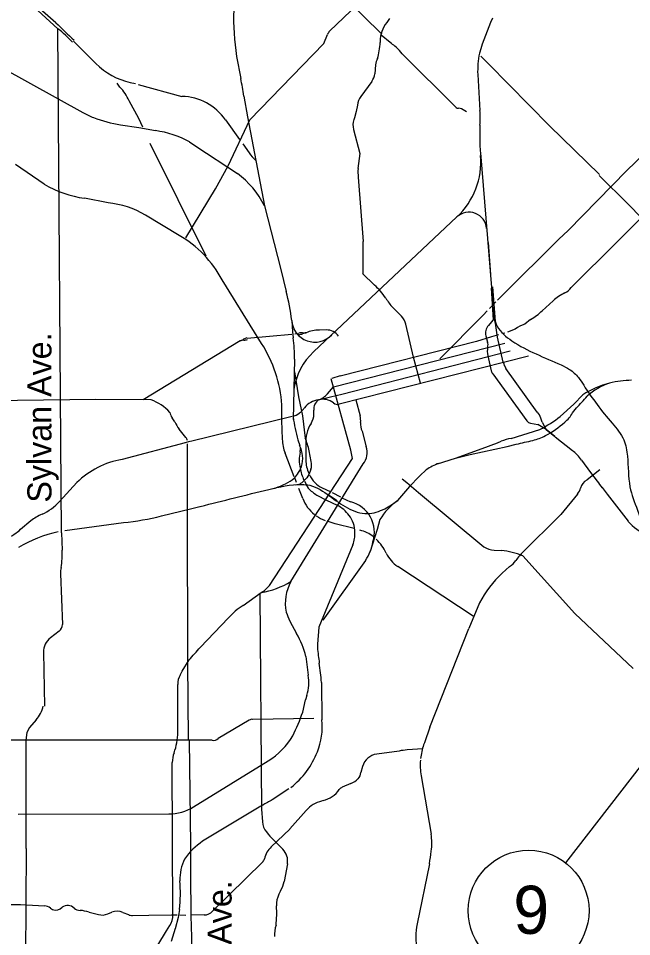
# Model space of a CAD drawing. Extents: x 105094 to 105814, y -291615 to -291123.
# Drawn here: x 105428.3 to 105459.11, y -291494.14 to -291448.01 of the extents above; entities that cross this region are included whole.
import ezdxf

# ---------------------------------------------------------------- set-up
doc = ezdxf.new("R2010")
doc.units = 0
doc.layers.add('G_BORDER', color=7, linetype='Continuous')
doc.layers.add('G_MAP', color=7, linetype='Continuous')

msp = doc.modelspace()

# ---------------------------------------------------------------- linework, layer by layer
at = {"layer": 'G_BORDER'}
msp.add_line((105461.154, -291483.504), (105455.794, -291490.435), dxfattribs=at)
msp.add_circle((105453.937, -291492.836), 3.035, dxfattribs=at)
at = {"layer": 'G_MAP'}
for p, q in [((105439.683, -291441.953), (105446.556, -291448.806)), ((105443.935, -291448.654), (105446.62, -291446.065)), ((105430.185, -291448.226), (105428.864, -291447.053)), ((105428.871, -291447.247), (105430.285, -291448.523)), ((105446.953, -291448.005), (105446.817, -291448.218)), ((105430.46, -291473.849), (105430.285, -291448.523)), ((105431.07, -291449.156), (105432.194, -291450.276)), ((105443.656, -291449.273), (105443.838, -291448.809)), ((105446.482, -291449.165), (105446.479, -291449.223)), ((105446.985, -291449.219), (105446.527, -291448.842)), ((105439.935, -291453.111), (105443.656, -291449.273)), ((105439.263, -291449.915), (105439.47, -291451.032)), ((105451.539, -291449.91), (105451.923, -291450.298)), ((105427.527, -291450.506), (105431.537, -291452.737)), ((105446.25, -291450.336), (105446.206, -291450.795)), ((105451.38, -291450.827), (105451.494, -291452.633)), ((105433.402, -291451.468), (105433.256, -291451.261)), ((105433.922, -291451.225), (105434.183, -291451.284)), ((105434.316, -291451.335), (105436.518, -291451.923)), ((105446.063, -291451.169), (105445.503, -291451.926)), ((105439.635, -291451.907), (105439.816, -291452.956)), ((105450.809, -291452.698), (105450.558, -291452.553)), ((105433.438, -291453.36), (105434.348, -291453.496)), ((105438.701, -291453.108), (105439.415, -291454.084)), ((105438.837, -291455.417), (105439.935, -291453.111)), ((105439.816, -291452.956), (105440.662, -291457.418)), ((105451.491, -291453.379), (105451.481, -291453.961)), ((105434.348, -291453.496), (105435.191, -291453.644)), ((105445.136, -291453.585), (105445.458, -291454.8)), ((105437.742, -291459.945), (105434.923, -291454.287)), ((105436.906, -291454.21), (105437.209, -291454.419)), ((105439.573, -291454.316), (105439.89, -291454.757)), ((105437.209, -291454.419), (105439.302, -291455.802)), ((105451.513, -291454.755), (105452.074, -291461.522)), ((105445.458, -291454.8), (105445.364, -291455.553)), ((105429.6, -291456.335), (105428.157, -291455.35)), ((105445.377, -291455.989), (105445.626, -291459.218)), ((105432.804, -291457.281), (105431.629, -291457.045)), ((105440.662, -291457.418), (105441.482, -291460.617)), ((105436.379, -291458.909), (105434.69, -291457.895)), ((105450.337, -291457.984), (105443.135, -291464.765)), ((105451.901, -291459.26), (105452.03, -291460.881)), ((105441.482, -291460.617), (105441.757, -291461.731)), ((105440.517, -291464.337), (105438.534, -291461.15)), ((105446.194, -291461.403), (105445.587, -291460.823)), ((105452.124, -291461.495), (105452.269, -291463.449)), ((105452.382, -291462.16), (105452.64, -291461.892)), ((105447.542, -291462.969), (105447.121, -291462.535)), ((105451.965, -291462.577), (105452.285, -291462.244)), ((105455.163, -291462.195), (105454.617, -291462.696)), ((105449.469, -291465.119), (105451.659, -291462.916)), ((105451.659, -291462.916), (105451.852, -291462.693)), ((105452.215, -291463.075), (105451.917, -291463.437)), ((105442.034, -291463.178), (105442.076, -291463.75)), ((105454.039, -291463.136), (105453.742, -291463.362)), ((105442.034, -291463.885), (105439.796, -291464.095)), ((105442.076, -291463.75), (105442.112, -291464.056)), ((105442.396, -291463.859), (105442.189, -291463.876)), ((105443.771, -291463.661), (105443.425, -291463.664)), ((105451.79, -291463.96), (105451.878, -291464.269)), ((105452.421, -291463.898), (105452.078, -291464.014)), ((105452.734, -291463.814), (105452.598, -291463.843)), ((105453.257, -291463.614), (105452.873, -291463.765)), ((105439.444, -291464.205), (105434.564, -291467.17)), ((105444.133, -291466.525), (105452.744, -291464.331)), ((105452.662, -291465.287), (105452.369, -291464.03)), ((105444.544, -291466.885), (105453.018, -291464.712)), ((105442.178, -291465.122), (105442.115, -291468.158)), ((105453.935, -291464.977), (105444.414, -291467.392)), ((105451.883, -291464.954), (105452.06, -291465.708)), ((105442.182, -291465.759), (105442.38, -291467.021)), ((105454.375, -291467.79), (105452.799, -291465.59)), ((105442.244, -291466.291), (105442.27, -291466.411)), ((105445.006, -291469.705), (105444.02, -291466.115)), ((105444.473, -291465.972), (105444.043, -291466.107)), ((105452.132, -291465.865), (105453.846, -291468.224)), ((105443.837, -291466.868), (105444.133, -291466.525)), ((105442.38, -291467.021), (105442.574, -291467.971)), ((105443.384, -291467.173), (105443.982, -291467.028)), ((105443.982, -291467.028), (105444.544, -291466.885)), ((105445.261, -291467.179), (105445.47, -291467.98)), ((105456.661, -291466.924), (105456.206, -291467.396)), ((105441.544, -291468.216), (105441.54, -291467.425)), ((105443.146, -291467.876), (105443.142, -291467.689)), ((105456.206, -291467.396), (105455.531, -291468.003)), ((105456.141, -291467.832), (105456.345, -291467.576)), ((105436.163, -291468.284), (105436.022, -291468.073)), ((105442.057, -291468.006), (105436.951, -291469.263)), ((105442.574, -291467.971), (105442.713, -291469.091)), ((105454.614, -291468.29), (105454.543, -291468.09)), ((105441.563, -291469.152), (105441.544, -291468.216)), ((105454.039, -291468.347), (105454.401, -291468.419)), ((105454.825, -291468.67), (105454.401, -291468.419)), ((105454.614, -291468.29), (105454.825, -291468.67)), ((105436.721, -291469.056), (105436.379, -291468.643)), ((105445.568, -291468.746), (105445.778, -291469.534)), ((105453.054, -291469.107), (105454.501, -291468.658)), ((105454.825, -291468.67), (105455.25, -291469.022)), ((105455.25, -291469.022), (105454.825, -291468.67)), ((105455.269, -291469.03), (105456.136, -291469.712)), ((105436.673, -291469.334), (105433.515, -291470.164)), ((105436.912, -291469.272), (105436.667, -291469.334)), ((105436.796, -291472.777), (105436.799, -291469.389)), ((105442.348, -291469.185), (105442.438, -291469.469)), ((105451.607, -291469.611), (105452.376, -291469.337)), ((105452.376, -291469.337), (105452.553, -291469.246)), ((105452.867, -291469.508), (105453.319, -291469.398)), ((105442.164, -291471.045), (105441.7, -291469.853)), ((105443.019, -291470.272), (105442.913, -291469.728)), ((105450.257, -291470.105), (105451.607, -291469.611)), ((105441.996, -291476.306), (105445.621, -291470.392)), ((105449.362, -291470.387), (105450.257, -291470.105)), ((105448.474, -291470.987), (105448.794, -291470.684)), ((105457.524, -291470.687), (105456.884, -291471.194)), ((105431.235, -291471.33), (105430.368, -291472.278)), ((105442.273, -291471.333), (105442.199, -291471.116)), ((105442.671, -291471.255), (105442.806, -291471.507)), ((105447.586, -291471.145), (105447.815, -291471.32)), ((105447.815, -291471.323), (105448.167, -291471.627)), ((105447.927, -291471.559), (105448.474, -291470.987)), ((105456.884, -291471.194), (105456.859, -291471.208)), ((105442.589, -291472.13), (105442.393, -291471.627)), ((105442.745, -291471.41), (105442.868, -291471.604)), ((105443.571, -291471.593), (105443.969, -291471.782)), ((105444.063, -291471.82), (105444.479, -291472.053)), ((105447.363, -291472.23), (105447.977, -291471.526)), ((105448.164, -291471.627), (105448.406, -291471.83)), ((105448.406, -291471.83), (105451.694, -291474.562)), ((105457.63, -291471.584), (105457.882, -291471.917)), ((105443.302, -291471.963), (105443.782, -291472.205)), ((105443.782, -291472.205), (105444.311, -291472.47)), ((105444.315, -291472.253), (105443.933, -291471.998)), ((105444.554, -291472.101), (105444.996, -291472.292)), ((105457.882, -291471.917), (105458.933, -291473.276)), ((105435.495, -291473.006), (105436.954, -291472.644)), ((105436.812, -291480.334), (105436.796, -291472.777)), ((105436.954, -291472.644), (105437.423, -291472.538)), ((105446.469, -291473.187), (105446.333, -291473.694)), ((105428.925, -291473.255), (105428.412, -291473.678)), ((105430.628, -291473.736), (105433.576, -291473.342)), ((105446.333, -291473.694), (105445.978, -291474.794)), ((105430.46, -291473.849), (105430.5, -291474.721)), ((105445.109, -291474.453), (105443.397, -291478.6)), ((105452.2, -291474.72), (105452.568, -291474.747)), ((105445.749, -291475.241), (105443.598, -291478.244)), ((105451.145, -291478.038), (105447.362, -291475.546)), ((105452.98, -291475.544), (105452.605, -291475.88)), ((105430.418, -291475.908), (105430.51, -291478.463)), ((105439.596, -291477.498), (105440.497, -291476.852)), ((105440.439, -291476.914), (105440.52, -291487.779)), ((105451.471, -291477.379), (105450.932, -291478.667)), ((105437.426, -291479.609), (105438.853, -291478.131)), ((105441.943, -291478.287), (105442.274, -291478.913)), ((105448.978, -291483.612), (105450.932, -291478.667)), ((105430.354, -291478.795), (105429.909, -291479.134)), ((105429.558, -291479.855), (105429.607, -291482.556)), ((105442.745, -291480.072), (105442.858, -291481.002)), ((105436.848, -291484.232), (105436.812, -291480.334)), ((105436.305, -291483.877), (105436.305, -291481.47)), ((105443.533, -291481.367), (105443.549, -291483.247)), ((105442.587, -291482.857), (105442.732, -291482.246)), ((105442.787, -291482.023), (105442.732, -291482.246)), ((105439.903, -291483.267), (105438.337, -291484.19)), ((105443.139, -291483.186), (105440.081, -291483.225)), ((105448.978, -291483.612), (105448.701, -291484.41)), ((105438.04, -291484.271), (105420.577, -291484.284)), ((105428.684, -291489.722), (105428.693, -291484.267)), ((105436.877, -291484.271), (105436.948, -291489.541)), ((105448.63, -291484.7), (105447.832, -291484.759)), ((105448.701, -291484.41), (105448.659, -291484.5)), ((105447.428, -291484.817), (105446.308, -291484.97)), ((105436.06, -291493.039), (105436.034, -291485.395)), ((105437.106, -291487.622), (105440.848, -291485.311)), ((105445.595, -291485.595), (105445.513, -291485.895)), ((105448.532, -291486.056), (105449.037, -291488.986)), ((105445.01, -291486.448), (105444.57, -291486.638)), ((105441.889, -291486.722), (105441.056, -291487.265)), ((105443.617, -291487.309), (105443.536, -291487.33)), ((105428.286, -291487.981), (105435.853, -291487.978)), ((105440.478, -291487.588), (105437.559, -291489.348)), ((105440.517, -291487.739), (105440.559, -291488.374)), ((105442.763, -291487.804), (105441.941, -291488.734)), ((105441.944, -291488.737), (105441.003, -291489.634)), ((105441.111, -291489.273), (105441.587, -291489.752)), ((105428.684, -291489.722), (105428.529, -291514.353)), ((105440.564, -291490.403), (105438.061, -291492.87)), ((105441.814, -291490.489), (105441.65, -291491.366)), ((105448.951, -291490.48), (105448.33, -291493.495)), ((105441.476, -291491.841), (105441.392, -291492.013)), ((105430.4, -291492.74), (105430.503, -291492.668)), ((105431.852, -291492.913), (105432.325, -291493.035)), ((105432.798, -291493), (105432.988, -291492.921)), ((105433.552, -291492.922), (105433.826, -291493.038)), ((105434.028, -291493.078), (105434.859, -291493.071)), ((105434.859, -291493.071), (105435.989, -291493.055)), ((105436.002, -291493.052), (105436.273, -291493.052)), ((105436.383, -291492.88), (105436.322, -291493.178)), ((105436.394, -291492.775), (105436.383, -291492.88)), ((105436.419, -291493.048), (105436.719, -291493.058)), ((105437.627, -291493.052), (105436.968, -291493.061)), ((105436.322, -291493.178), (105436.176, -291493.743)), ((105434.261, -291496.294), (105435.744, -291493.849)), ((105435.744, -291493.849), (105435.909, -291493.586)), ((105436.176, -291493.74), (105435.97, -291494.385))]:
    msp.add_line(p, q, dxfattribs=at)
for points in [[(105471.669, -291445.853), (105471.33, -291446.221), (105468.414, -291449.206), (105465.61, -291451.938), (105463.22, -291454.38), (105458.379, -291459.237), (105456.07, -291461.521)], [(105452.64, -291461.892), (105455.457, -291459.092), (105455.925, -291458.656), (105458.88, -291455.656), (105459.723, -291454.825), (105463.482, -291451.066), (105464.151, -291450.417), (105465.219, -291449.141)], [(105450.291, -291452.486), (105447.583, -291449.785), (105447.444, -291449.613)], [(105451.923, -291450.298), (105454.988, -291453.401), (105457.507, -291455.849)], [(105434.545, -291453.464), (105434.348, -291453.037), (105433.86, -291452.146)], [(105445.345, -291452.366), (105445.345, -291452.372), (105445.277, -291452.691), (105445.196, -291452.995), (105445.159, -291453.095)], [(105436.706, -291459.038), (105438.201, -291456.574), (105438.837, -291455.417)], [(105457.478, -291455.895), (105458.935, -291457.348), (105461.619, -291460.093), (105463.046, -291461.488), (105464.351, -291462.774)], [(105445.619, -291460.823), (105445.629, -291459.958), (105445.626, -291459.218)], [(105452.049, -291461.556), (105452.153, -291463.161), (105452.13, -291463.197)], [(105448.513, -291466.333), (105448.151, -291465.028), (105447.764, -291463.376)], [(105452.075, -291464.004), (105451.319, -291464.243), (105444.473, -291465.978)], [(105434.964, -291467.178), (105432.187, -291467.157), (105424.304, -291467.257), (105420.212, -291467.19)], [(105442.748, -291469.398), (105442.751, -291470.083), (105442.749, -291470.211)], [(105450.257, -291470.105), (105450.993, -291469.921), (105452.867, -291469.508)], [(105440.911, -291476.5), (105445.096, -291470.118), (105445.006, -291469.705)], [(105456.595, -291470.196), (105457.042, -291470.829), (105457.388, -291471.261)], [(105456.398, -291471.903), (105455.554, -291472.941), (105453.571, -291474.905), (105453.477, -291475.009)], [(105445.17, -291473.639), (105444.214, -291473.403), (105443.808, -291473.267)], [(105453.642, -291475.011), (105456.257, -291477.908), (105459.185, -291480.671)], [(105443.397, -291478.6), (105443.323, -291479.446), (105443.323, -291479.623)], [(105436.426, -291480.997), (105436.535, -291480.799), (105436.874, -291480.237)], [(105429.195, -291483.249), (105428.858, -291483.641), (105428.732, -291483.88), (105428.671, -291484.264)], [(105436.948, -291489.541), (105436.948, -291490.972), (105436.971, -291493.09), (105437.006, -291494.166), (105437.006, -291494.818), (105437.01, -291498.067), (105436.971, -291505.559), (105437.013, -291510.468)], [(105427.482, -291492.532), (105428.412, -291492.528), (105429.612, -291492.597)]]:
    msp.add_lwpolyline(points, dxfattribs=at)
for centre, radius, start, end in [((105451.848, -291447.961), 12.736, 178.3296, 188.8235), ((105447.664, -291430.771), 24.701, 224.9607, 227.9176), ((105447.808, -291449.103), 1.327, 138.2348, 182.6801), ((105466.386, -291454.248), 15.582, 156.3243, 163.2541), ((105422.645, -291457.597), 11.862, 45.0555, 49.9037), ((105444.202, -291448.931), 0.384, 133.994, 161.5815), ((105443.104, -291449.065), 3.378, 343.4559, 357.3213), ((105444.53, -291452.541), 4.13, 45.1361, 53.5308), ((105447.054, -291450.409), 0.808, 151.7395, 174.7801), ((105455.916, -291450.648), 4.539, 168.6953, 182.25), ((105434.698, -291447.765), 3.546, 225.0895, 257.3608), ((105424.419, -291454.317), 15.406, 9.0006, 12.3132), ((105445.459, -291450.723), 0.751, 323.509, 354.5267), ((105431.907, -291452.972), 2.121, 22.9368, 45.1968), ((105436.476, -291454.605), 2.682, 33.9214, 89.0875), ((105446.155, -291452.409), 0.811, 143.5258, 176.9523), ((105433.72, -291448.804), 4.498, 240.956, 248.4911), ((105450.389, -291452.385), 0.141, 225.7595, 281.2306), ((105450.444, -291452.751), 0.229, 59.9057, 96.7289), ((105442.98, -291452.969), 8.521, 357.2428, 2.2611), ((105435.026, -291444.819), 8.688, 250.1189, 259.468), ((105445.923, -291453.377), 0.814, 159.7058, 194.7775), ((105434.445, -291458.792), 5.201, 61.7657, 81.7577), ((105458.364, -291454.075), 6.885, 179.0483, 185.6628), ((105442.026, -291453.223), 2.63, 215.6853, 226.8997), ((105447.72, -291455.204), 3.817, 313.2748, 4.7334), ((105447.323, -291455.713), 1.965, 175.3256, 188.0685), ((105436.656, -291459.409), 4.474, 26.432, 53.7392), ((105432.34, -291451.764), 5.329, 239.0627, 262.3292), ((105432.446, -291461.588), 4.322, 58.7155, 85.2448), ((105450.945, -291458.629), 0.886, 4.7334, 133.2748), ((105433.548, -291463.786), 5.64, 27.8676, 59.8615), ((105443.194, -291464.551), 4.349, 34.9388, 46.3783), ((105455.428, -291461.13), 0.752, 296.4072, 328.6737), ((105431.946, -291464.364), 10.158, 6.7077, 15.0247), ((105448.927, -291460.783), 2.516, 210.501, 224.1131), ((105456.648, -291463.813), 2.196, 113.7889, 132.5456), ((105446.92, -291463.573), 0.867, 13.1391, 44.1335), ((105446.36, -291464.498), 6.028, 4.4503, 13.6063), ((105452.287, -291460.23), 3.393, 301.0858, 313.3698), ((105443.197, -291463.106), 1.165, 183.5224, 316.8845), ((105452.312, -291463.81), 0.543, 136.566, 195.9371), ((105454.799, -291465.986), 2.829, 111.9397, 123.0151), ((105442.522, -291464.593), 0.786, 86.3427, 99.7128), ((105442.271, -291463.126), 0.786, 279.7128, 293.083), ((105442.622, -291463.023), 0.786, 266.3427, 279.7129), ((105442.887, -291464.573), 0.786, 99.7128, 113.083), ((105443.446, -291465.517), 1.853, 90.6471, 111.8946), ((105443.779, -291464.423), 0.763, 36.5429, 90.6383), ((105439.204, -291463.434), 0.808, 287.3242, 300.5132), ((105439.685, -291464.976), 0.808, 94.1351, 107.3242), ((105440.024, -291464.826), 0.808, 107.3242, 120.5133), ((105439.568, -291463.365), 0.808, 274.1351, 287.3241), ((105434.989, -291467.884), 6.567, 4.006, 32.6848), ((105431.902, -291465.221), 10.276, 0.5487, 6.5068), ((105451.393, -291464.408), 0.505, 346.6504, 16.0118), ((105445.226, -291467.065), 3.109, 132.282, 172.151), ((105452.792, -291464.741), 0.934, 166.6319, 193.1952), ((105453.492, -291465.094), 0.852, 193.086, 215.6061), ((105452.485, -291465.608), 0.437, 193.2388, 216.0236), ((105459.536, -291473.779), 7.608, 93.1821, 101.6109), ((105459.167, -291470.749), 4.573, 104.7259, 123.2294), ((105459.118, -291469.5), 3.363, 109.3325, 131.777), ((105434.217, -291469.345), 2.292, 42.3205, 70.9785), ((105443.498, -291468.2), 1.033, 96.3374, 142.876), ((105443.679, -291467.626), 0.54, 122.9949, 186.6814), ((105442.975, -291466.075), 1.172, 290.4657, 317.4066), ((105443.605, -291468.016), 0.871, 52.7395, 104.6959), ((105449.423, -291460.732), 9.734, 315.3206, 319.9777), ((105441.997, -291467.065), 0.849, 311.6063, 322.9384), ((105444.338, -291467.094), 0.307, 228.0877, 284.1637), ((105434.43, -291468.065), 1.505, 9.8617, 10.1015), ((105436.635, -291467.664), 0.737, 191.2113, 213.6497), ((105450.769, -291466.824), 8.746, 188.0304, 195.6625), ((105441.879, -291467.151), 0.87, 288.8397, 314.2527), ((105442.303, -291467.898), 0.843, 326.4954, 1.5496), ((105444.577, -291468.214), 0.924, 353.977, 14.7047), ((105454.088, -291468.147), 0.459, 7.1799, 51.2401), ((105451.497, -291462.802), 6.582, 297.1505, 307.7962), ((105454.883, -291467.155), 1.428, 307.3909, 331.7423), ((105438.255, -291467.266), 2.327, 205.9518, 216.2766), ((105444.368, -291469.253), 1.627, 146.855, 185.1137), ((105446.318, -291468.398), 0.828, 173.9904, 204.8755), ((105454.101, -291468.038), 0.315, 216.0251, 258.6533), ((105452.805, -291465.123), 4.326, 297.2452, 312.9244), ((105436.487, -291469.25), 0.304, 5.4421, 39.6144), ((105453.586, -291466.744), 2.527, 282.8593, 298.3179), ((105443.599, -291469.116), 2.037, 181.0163, 201.2319), ((105441.126, -291470.125), 1.461, 344.2075, 26.6578), ((105437.406, -291471.111), 5.678, 14.1029, 20.8372), ((105444.942, -291469.823), 0.886, 320.0289, 19.9621), ((105454.53, -291475.398), 6.461, 103.2036, 107.8115), ((105449.075, -291449.013), 20.821, 281.7584, 284.1019), ((105444.24, -291470.18), 1.828, 167.9986, 193.2757), ((105441.57, -291469.611), 0.902, 347.9496, 3.0839), ((105454.699, -291471.537), 2.322, 35.2587, 51.7687), ((105434.268, -291474.449), 4.351, 99.9687, 134.197), ((105444.226, -291470.231), 1.477, 179.2032, 205.2501), ((105442.241, -291470.423), 0.792, 342.5341, 11.0167), ((105450.497, -291473.235), 3.068, 110.5997, 123.7127), ((105444.531, -291470.274), 2.096, 188.9517, 206.2455), ((105444.142, -291470.388), 1.333, 204.5352, 244.6404), ((105457.191, -291471.797), 0.676, 119.4036, 163.4128), ((105459.428, -291469.984), 2.407, 212.06, 221.6804), ((105444.398, -291470.197), 2.079, 222.6016, 238.1781), ((105455.836, -291471.445), 0.725, 320.842, 347.3375), ((105428.336, -291470.423), 2.752, 294.7949, 317.6026), ((105444.397, -291471.426), 1.94, 201.2779, 231.1949), ((105444.589, -291473.838), 1.599, 342.8285, 75.2496), ((105449.008, -291474.665), 2.938, 124.0484, 149.7976), ((105443.639, -291473.886), 1.567, 35.3005, 64.6116), ((105430.275, -291474.894), 2.123, 111.6884, 129.4666), ((105432.147, -291459.534), 13.882, 275.9089, 283.954), ((105445.102, -291470.077), 3.455, 237.9369, 246.305), ((105443.758, -291473.857), 1.454, 1.2183, 37.0898), ((105427.069, -291472.308), 1.918, 290.2692, 314.4275), ((105461.346, -291471.055), 3.279, 222.6382, 243.4121), ((105432.077, -291481.255), 7.666, 103.4675, 119.5274), ((105443.603, -291473.882), 1.61, 339.2607, 2.0072), ((105445.126, -291475.293), 1.603, 50.9288, 77.9317), ((105443.587, -291473.847), 2.572, 327.1913, 349.6201), ((105444.767, -291475.797), 2.219, 24.5863, 46.8653), ((105452.287, -291473.55), 1.173, 239.6355, 265.7452), ((105426.067, -291474.925), 4.437, 351.3036, 2.6368), ((105448.245, -291474.205), 1.606, 204.6144, 236.6235), ((105452.324, -291478.057), 3.319, 66.5999, 85.7829), ((105455.1, -291476.465), 2.18, 138.1116, 145.9282), ((105452.441, -291474.667), 1.03, 301.5337, 325.9475), ((105431.479, -291475.87), 1.062, 165.0431, 182.0406), ((105456.069, -291479.678), 5.141, 132.3647, 153.4267), ((105439.762, -291472.505), 4.409, 279.5939, 300.4334), ((105443.857, -291477.371), 2.145, 150.2301, 192.462), ((105439.956, -291475.798), 1.185, 297.1712, 323.6617), ((105441.291, -291480.239), 3.223, 121.7281, 139.1471), ((105443.926, -291477.239), 2.243, 195.3765, 207.8494), ((105430.113, -291478.479), 0.398, 307.2736, 2.2931), ((105430.45, -291479.843), 0.891, 127.3166, 180.7795), ((105438.487, -291481.129), 4.387, 13.9301, 30.3321), ((105430.673, -291474.224), 8.637, 315.8802, 321.4301), ((105456.516, -291478.376), 13.251, 185.4004, 188.7925), ((105403.281, -291485.591), 40.473, 5.9897, 7.3661), ((105437.291, -291481.47), 0.985, 151.298, 180.0017), ((105440.868, -291481.377), 2.025, 341.3891, 10.6482), ((105427.971, -291482.195), 1.616, 319.2705, 347.0802), ((105433.917, -291479.937), 9.148, 333.2972, 341.3865), ((105440.035, -291483.427), 0.207, 77.1796, 129.4175), ((105440.292, -291483.607), 3.277, 337.6643, 6.3011), ((105433.514, -291483.907), 2.792, 339.0883, 0.6219), ((105438.116, -291483.963), 0.317, 256.1496, 314.2534), ((105438.893, -291482.146), 3.72, 301.7011, 329.2476), ((105448.087, -291487.965), 3.216, 94.5584, 101.8294), ((105453.644, -291485.903), 5.179, 164.287, 172.1756), ((105437.467, -291485.398), 1.434, 159.8451, 179.9094), ((105439.464, -291483.384), 4.129, 307.7111, 339.1755), ((105446.425, -291485.822), 0.86, 97.7828, 164.703), ((105451.52, -291485.542), 3.031, 174.8854, 189.7624), ((105445.015, -291485.854), 0.5, 314.3964, 355.3139), ((105444.538, -291485.355), 1.19, 293.3609, 313.9576), ((105443.259, -291485.919), 1.435, 284.4326, 324.4227), ((105444.707, -291486.955), 0.345, 113.3711, 144.4126), ((105445.645, -291495.643), 9.553, 118.7119, 122.081), ((105443.921, -291488.826), 1.545, 104.4193, 138.5629), ((105435.852, -291485.591), 2.387, 270.0239, 301.707), ((105441.415, -291488.318), 0.858, 183.7117, 221.1226), ((105442.463, -291487.743), 2.042, 213.9123, 228.529), ((105439.624, -291492.34), 3.636, 124.6158, 144.7645), ((105446.359, -291489.447), 2.717, 351.514, 9.7714), ((105441.85, -291490.521), 1.226, 133.6419, 166.1446), ((105440.999, -291490.337), 0.83, 349.4018, 44.8158), ((105443.008, -291489.258), 6.067, 348.3756, 354.4145), ((105438.734, -291491.27), 2.32, 153.7101, 181.6617), ((105440.322, -291490.158), 0.344, 314.6196, 348.275), ((105428.668, -291491.943), 7.771, 353.8527, 4.4766), ((105440.566, -291491.237), 1.092, 326.4437, 353.215), ((105442.45, -291492.538), 1.181, 153.633, 183.0307), ((105429.584, -291493.09), 0.494, 49.4082, 86.7367), ((105430.781, -291493.064), 0.484, 48.0775, 125.0107), ((105435.118, -291492.928), 6.162, 354.067, 3.0514), ((105430.169, -291492.409), 0.404, 229.3338, 304.9516), ((105431.427, -291492.345), 0.483, 228.0951, 267.0089), ((105431.316, -291494.496), 1.671, 71.2848, 87.0388), ((105432.511, -291492.315), 0.743, 255.542, 292.7632), ((105433.269, -291493.589), 0.725, 66.988, 112.7624), ((105434.023, -291492.572), 0.506, 247.0248, 270.4821), ((105435.069, -291493.059), 0.992, 327.8944, 1.1952), ((105437.618, -291492.421), 0.631, 270.8305, 314.5965), ((105451.357, -291494.118), 3.09, 168.3702, 192.9718), ((105443.109, -291494.128), 1.945, 163.1686, 180.4045)]:
    msp.add_arc(centre, radius, start, end, dxfattribs=at)
for points in [[(105452.074, -291461.522), (105452.139, -291462.56), (105452.363, -291463.474), (105453.095, -291464.208), (105455.567, -291465.415), (105455.997, -291465.645), (105456.439, -291466.049), (105456.706, -291466.439), (105458.129, -291468.348), (105458.72, -291469.189), (105458.903, -291470.005), (105459.03, -291471.542), (105459.405, -291472.708), (105460.608, -291476.478)], [(105441.125, -291471.632), (105441.716, -291471.395), (105442.156, -291471.101), (105442.381, -291470.829), (105442.5, -291470.613), (105442.532, -291470.522)], [(105442.994, -291470.663), (105442.843, -291471.003), (105442.574, -291471.307), (105442.447, -291471.402), (105442.228, -291471.456)], [(105437.437, -291472.528), (105440.878, -291471.675), (105442.535, -291471.424), (105442.943, -291471.467), (105443.933, -291471.998), (105444.842, -291472.606), (105445.832, -291472.889), (105446.706, -291472.64), (105447.363, -291472.23)]]:
    msp.add_spline(points, degree=3, dxfattribs=at)

# ---------------------------------------------------------------- texts
at = {"layer": 'G_BORDER'}
msp.add_text('9', height=2.416, dxfattribs=at).set_placement((105453.171, -291494.002))
at = {"layer": 'G_MAP'}
for s, p in [('Sylvan Ave.', (105429.963, -291472.337)), ('Beckley Ave.', (105439.014, -291500.67))]:
    msp.add_text(s, height=1.21107, rotation=90, dxfattribs=at).set_placement(p)

doc.saveas('drawing.dxf')
